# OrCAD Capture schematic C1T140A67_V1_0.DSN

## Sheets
1 000_note: title: Telink-Semi; rev: V1.0; note: C1T140A67
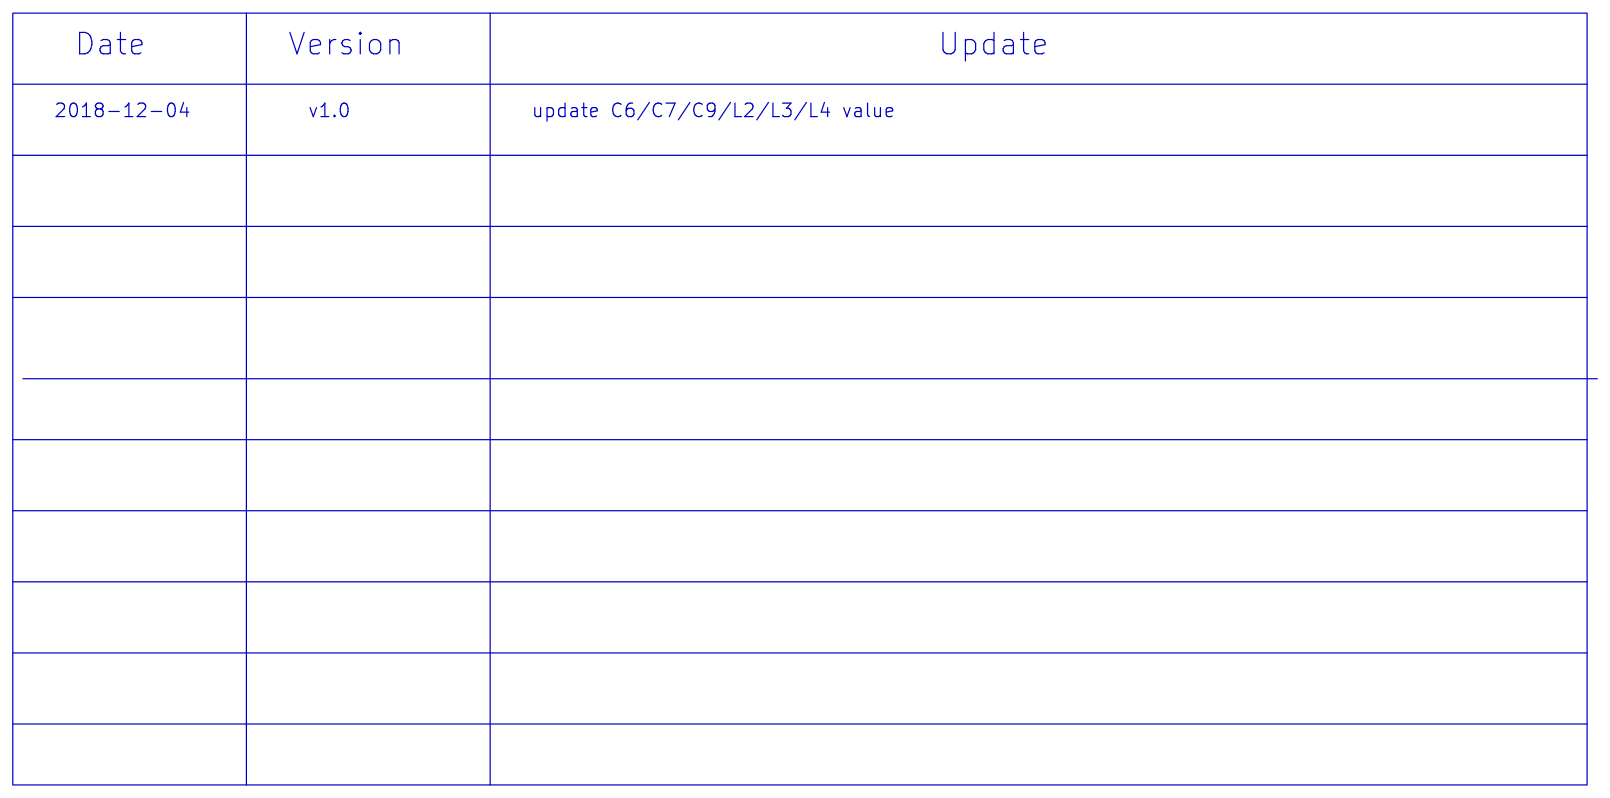
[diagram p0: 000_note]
2 001_chip: size A4
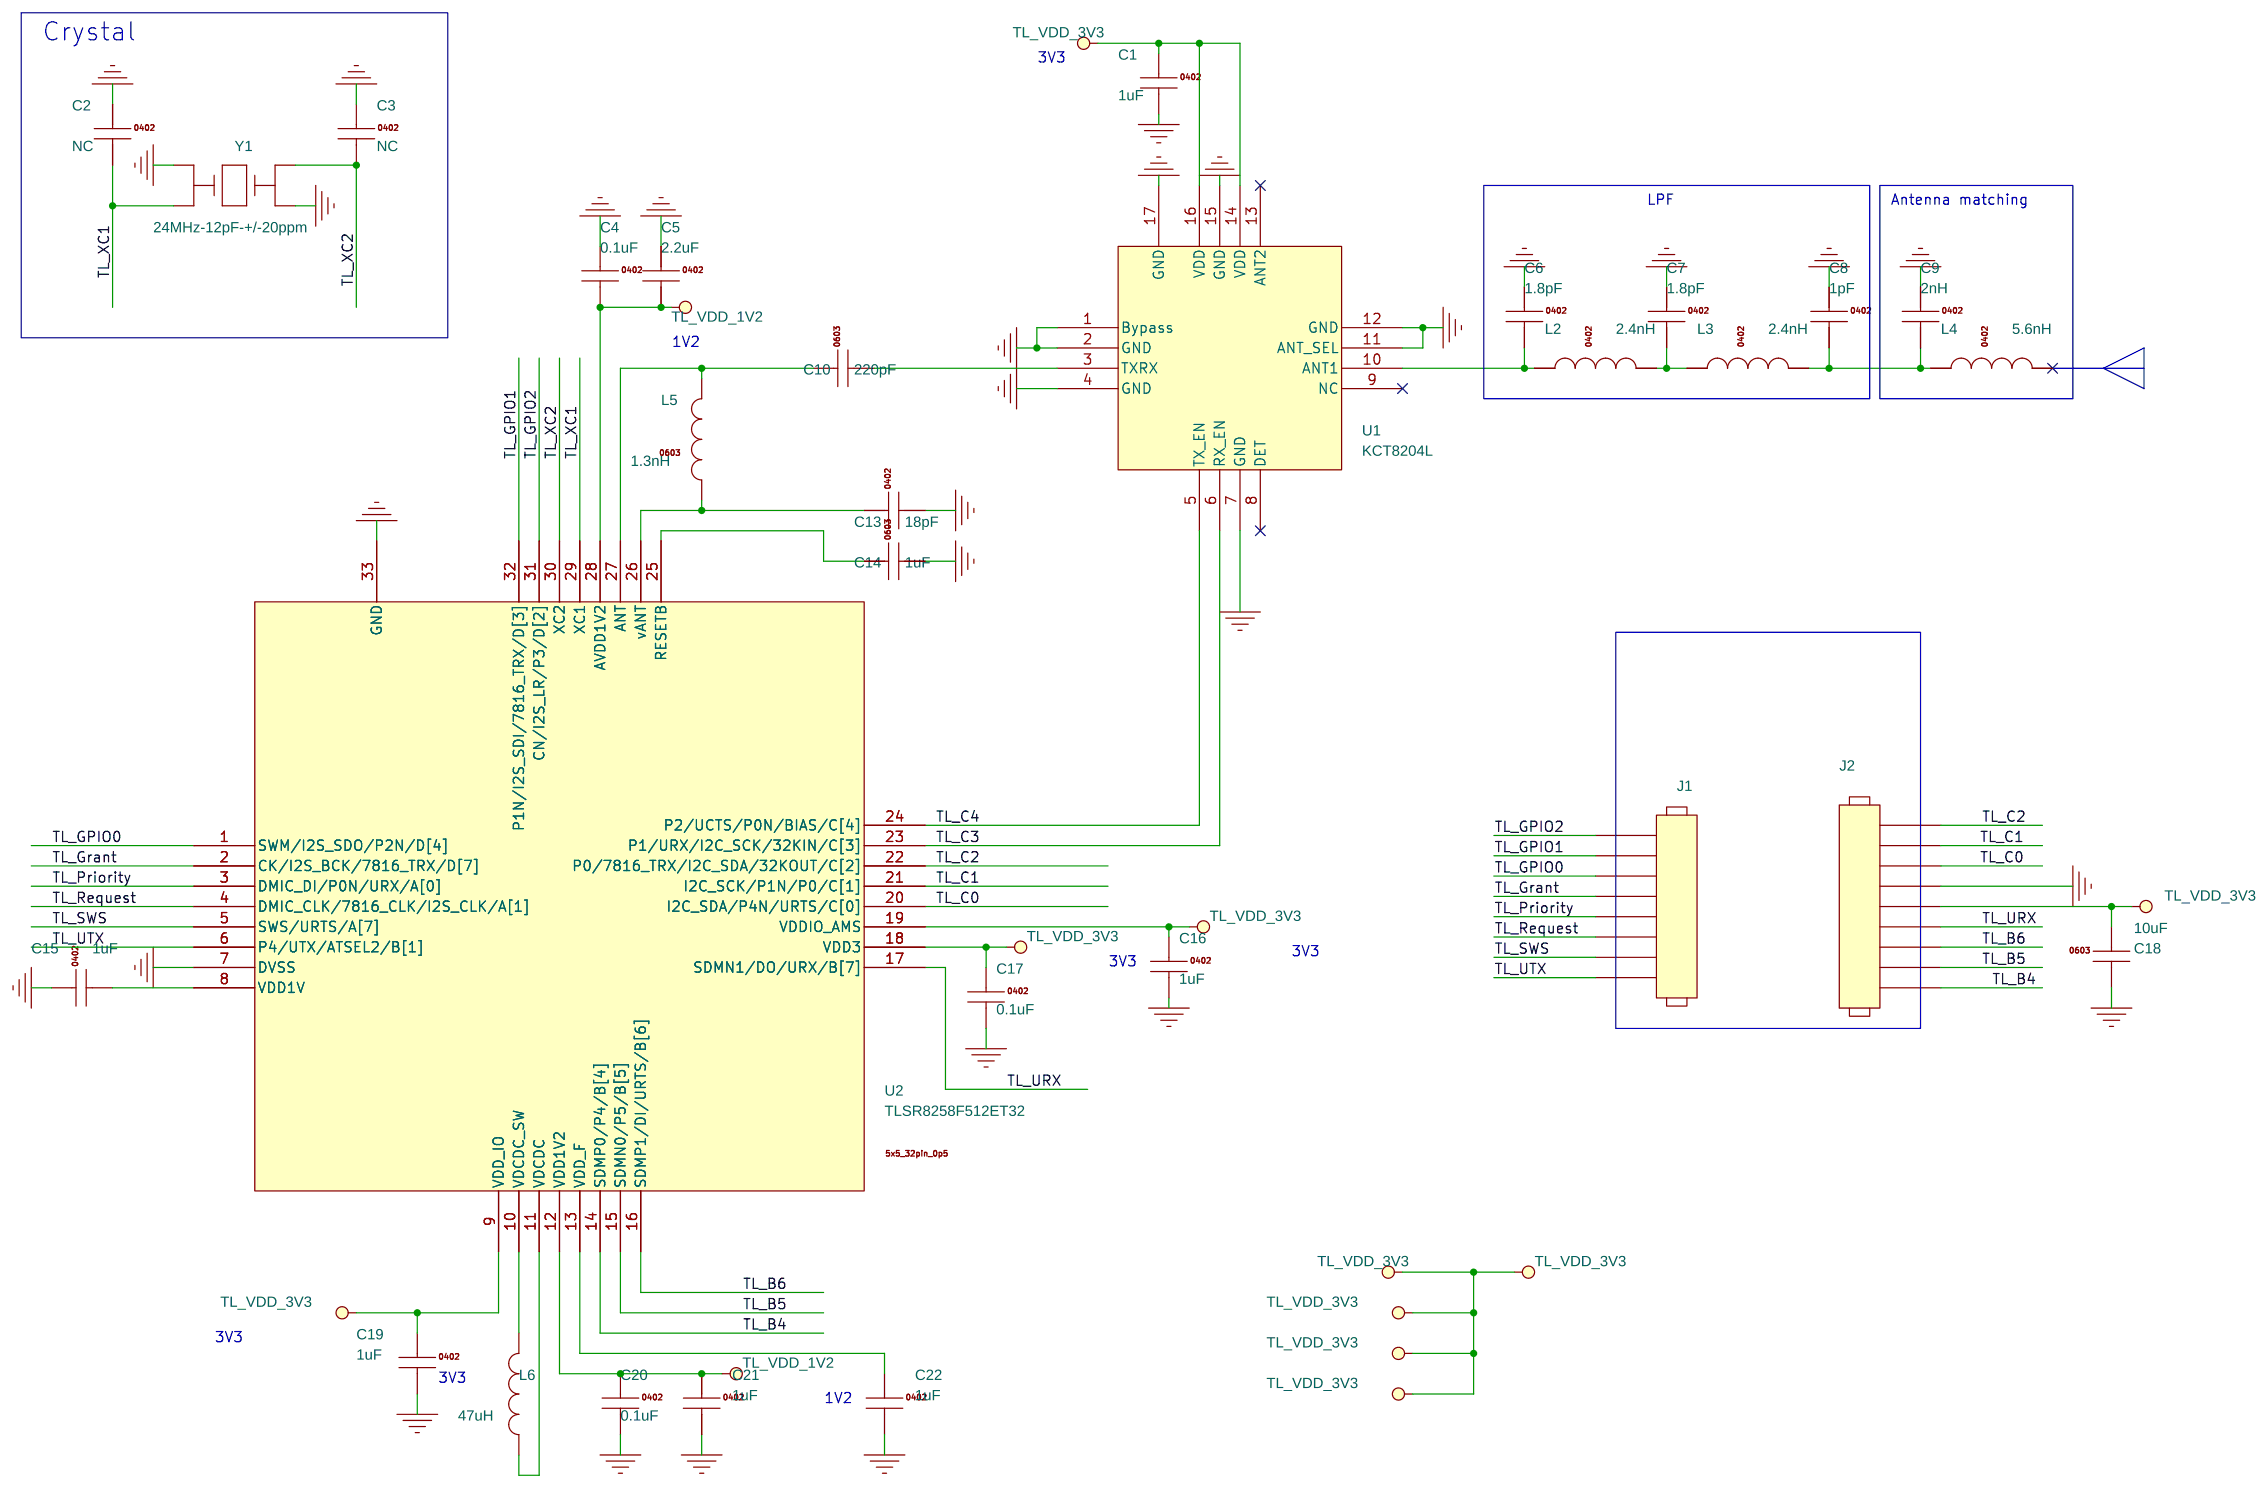
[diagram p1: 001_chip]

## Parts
C1  1uF  [0201]
C2  NC  [0201]
C3  NC  [0201]
C4  0.1uF  [0201]
C5  2.2uF  [0201]
C6  1.8pF  [0201]
C7  1.8pF  [0201]
C8  1pF  [0201]
C9  2nH  [0201]
C10  220pF  [0201]
C13  18pF  [0201]
C14  1uF  [0201]
C15  1uF  [0201]
C16  1uF  [0201]
C17  0.1uF  [0201]
C18  10uF  [0402]
C19  1uF  [0201]
C20  0.1uF  [0201]
C21  1uF  [0201]
C22  1uF  [0201]
J1  HEADER 8  [hdr_1p5_1x8]
J2  HEADER 9  [hdr_1p5_1x9]
L2  2.4nH  [0201]
L3  2.4nH  [0201]
L4  5.6nH  [0201]
L5  1.3nH  [0201]
L6  47uH  [0805L]
U1  KCT8204L  [qfn_3x3_16pin_0p5_1p70x1p70]
U2  TLSR8258F512ET32  [qfn_5x5_32pin_0p5_2p50x2p50]
Y1  24MHz-12pF-+/-20ppm  [osccc200x250x080]

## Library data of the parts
C1 C4 C5 C16 C17 C19-C22 = C1005X5R1C104K
C2 C3 = C1005_NC
C6-C9 = C1005C0G1H020C
C10 = C1608_NC
C13 = C1005C0G1H100D
C14 = C1608X5R1C105M
C15 = C1005X5R1C105K
C18 = C1608X5R0J106M
J1 = HEADER_8
J2 = HEADER_9
L2-L4 = MLK1005S3N3ST
L5 = MLK1608_000R
L6 = IND_0
U1 = KCT8204L
U2 = TLSR8258F512ET32
Y1 = CRYSTAL4_SM_0

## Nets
GND: C1.2 C2.1 C3.1 C4.1 C5.1 C6.1 C7.1 C8.1 C9.1 C13.2 C14.2 C15.1 C16.2 C17.2 C18.2 C19.2 C20.2 C21.2 C22.2 J2.4 U1.1(Bypass) U1.2(GND) U1.4(GND) U1.7(GND) U1.11(ANT_SEL) U1.12(GND) U1.15(GND) U1.17(GND) U2.7(DVSS) U2.33(GND) Y1.2 Y1.4
PAVDD: C1.1 C16.1 C17.1 C18.1 C19.1 J2.5 U1.14(VDD) U1.16(VDD) U2.9(VDD_IO) U2.18(VDD3) U2.19(VDDIO_AMS)
TL_B4: J2.9 U2.14(SDMP0/P4/B[4])
TL_B5: J2.8 U2.15(SDMN0/P5/B[5])
TL_B6: J2.7 U2.16(SDMP1/DI/URTS/B[6])
TL_C0: J2.3 U2.20(I2C_SDA/P4N/URTS/C[0])
TL_C1: J2.2 U2.21(I2C_SCK/P1N/P0/C[1])
TL_C2: J2.1 U2.22(P0/7816_TRX/I2C_SDA/32KOUT/C[2])
TL_C3: U1.6(RX_EN) U2.23(P1/URX/I2C_SCK/32KIN/C[3])
TL_C4: U1.5(TX_EN) U2.24(P2/UCTS/P0N/BIAS/C[4])
TL_GPIO0: J1.3 U2.1(SWM/I2S_SDO/P2N/D[4])
TL_GPIO1: J1.2 U2.32(P1N/I2S_SDI/7816_TRX/D[3])
TL_GPIO2: J1.1 U2.31(CN/I2S_LR/P3/D[2])
TL_Grant: J1.4 U2.2(CK/I2S_BCK/7816_TRX/D[7])
TL_Priority: J1.5 U2.3(DMIC_DI/P0N/URX/A[0])
TL_Request: J1.6 U2.4(DMIC_CLK/7816_CLK/I2S_CLK/A[1])
TL_SWS: J1.7 U2.5(SWS/URTS/A[7])
TL_URX: J2.6 U2.17(SDMN1/DO/URX/B[7])
TL_UTX: J1.8 U2.6(P4/UTX/ATSEL2/B[1])
TL_VDD_1V2: C4.2 C5.2 C20.1 C21.1 U2.12(VDD1V2) U2.28(AVDD1V2)
TL_XC1: C2.2 U2.29(XC1) Y1.3
TL_XC2: C3.2 U2.30(XC2) Y1.1
N19743728: C15.2 U2.8(VDD1V)
N19743785: L6.1 U2.11(VDCDC)
N19743791: L6.2 U2.10(VDCDC_SW)
N19743805: C22.1 U2.13(VDD_F)
N19743930: C10.1 L5.2 U2.27(ANT)
N19743949: C13.1 L5.1 U2.26(vANT)
N19743951: C14.1 U2.25(RESETB)
N19744088: C8.2 C9.2 L3.2 L4.1
N19744116: C7.2 L2.2 L3.1
N19750217: C6.2 L2.1 U1.10(ANT1)
N19756722: C10.2 U1.3(TXRX)

Not connected (* = marked no-connect by the designer): L4 2*; U1 8(DET)* 9(NC)* 13(ANT2)*

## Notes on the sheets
sheet 1
- Date
- Version
- Update
- 2018-12-04
- v1.0
- update C6/C7/C9/L2/L3/L4 value
sheet 2
- Crystal
- 3V3
- LPF
- Antenna matching
- 1V2
- 3V3
- 3V3
- 3V3
- 3V3
- 1V2
